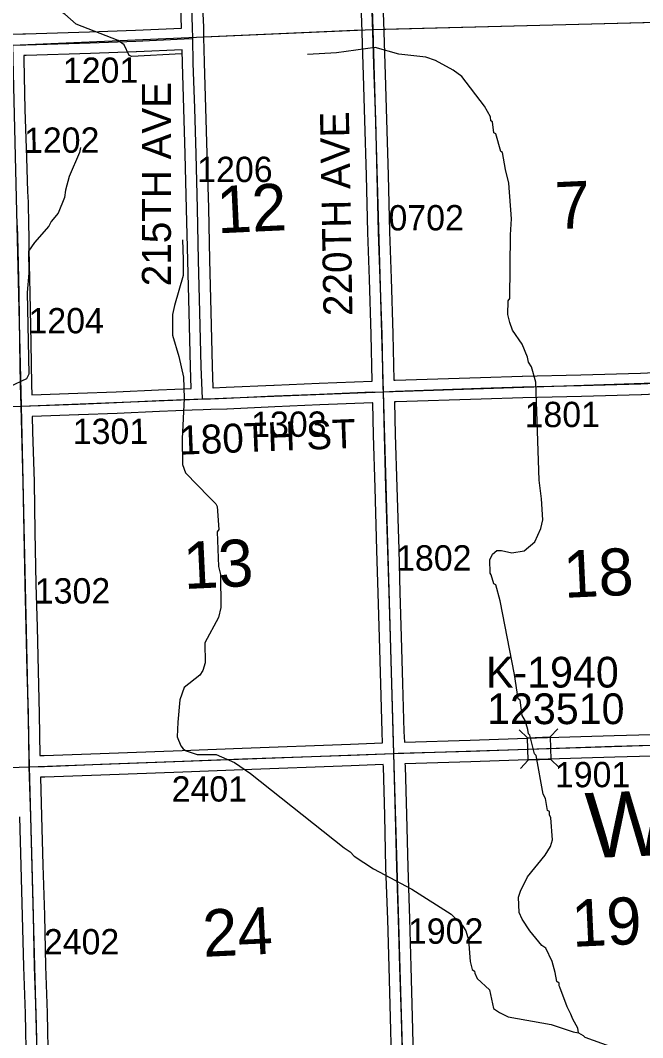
# Model space of a CAD drawing. Extents: x 128.7 to 185.5, y -21.4 to 12.6.
# Drawn here: x 145.06 to 146.778, y -5.142 to -2.33 of the extents above; entities that cross this region are included whole.
import ezdxf

# ---------------------------------------------------------------- set-up
doc = ezdxf.new("R2010")
doc.units = 0
for name, color, linetype in [('tdCoHydroRiver', 7, 'Continuous'), ('tdCoSecRdNmbr', 7, 'Continuous'), ('tdCoSecRdTxt', 7, 'Continuous'), ('tdCoSecRteBand', 7, 'Continuous'), ('tdCoSecRteCL', 7, 'Continuous'), ('tdCoSectLine', 7, 'Continuous'), ('tdCoSectLinePart', 7, 'Continuous'), ('tdCoSectNmbr', 7, 'Continuous'), ('tdCoStrucSec', 7, 'Continuous'), ('tdCoStrucSecCoName', 7, 'Continuous'), ('tdCoStrucSecFHWANum', 7, 'Continuous'), ('tdCoSurfAsphalt', 7, 'Continuous'), ('tdCoSurfGravel', 7, 'Continuous'), ('tdCoTwpBndryShd', 7, 'Continuous'), ('tdCoTwpNameTxt', 7, 'Continuous')]:
    doc.layers.add(name, color=color, linetype=linetype)

msp = doc.modelspace()

# ---------------------------------------------------------------- linework, layer by layer
at = {"layer": 'tdCoHydroRiver'}
for points in [[(145.5048, -2.4228), (145.3677, -2.4304), (145.3597, -2.4275), (145.3461, -2.398), (145.33, -2.3859), (145.2133, -2.3408), (145.1824, -2.3134), (145.1453, -2.2894), (145.0956, -2.2657), (144.9806, -2.2222)], [(146.6004, -5.128), (146.5984, -5.1154), (146.585, -5.0906), (146.5798, -5.0766), (146.5696, -5.0564), (146.5489, -5.0018), (146.5472, -4.9987), (146.547, -4.9909), (146.5405, -4.9863), (146.5365, -4.9612), (146.5277, -4.9315), (146.5107, -4.8942), (146.4994, -4.8867), (146.4665, -4.8467), (146.4449, -4.8143), (146.4364, -4.7956), (146.435, -4.7531), (146.4408, -4.7371), (146.46, -4.697), (146.5085, -4.637), (146.5235, -4.6129), (146.5293, -4.5953), (146.5241, -4.534), (146.5207, -4.5262), (146.5204, -4.5167), (146.5155, -4.5137), (146.5097, -4.4808), (146.503, -4.4684), (146.4837, -4.3617), (146.4788, -4.3571), (146.4661, -4.3055), (146.4628, -4.3024), (146.4608, -4.2898), (146.4537, -4.2648), (146.4454, -4.2509), (146.4392, -4.2085), (146.4344, -4.2055), (146.4243, -4.138), (146.3845, -3.9341), (146.372, -3.8903), (146.3671, -3.8873), (146.36, -3.8623), (146.3567, -3.8577), (146.3555, -3.8214), (146.3629, -3.8054), (146.3752, -3.7955), (146.3878, -3.7951), (146.4164, -3.8021), (146.4509, -3.7962), (146.4801, -3.7716), (146.4963, -3.7348), (146.5018, -3.7109), (146.4983, -3.6526), (146.4919, -3.6008), (146.483, -3.3296), (146.4705, -3.2874), (146.4622, -3.2751), (146.4602, -3.2609), (146.4448, -3.2251), (146.4183, -3.1865), (146.4113, -3.1647), (146.4058, -3.1428), (146.4062, -3.1049), (146.4107, -3.0984), (146.4128, -2.9232), (146.4161, -2.8789), (146.4081, -2.7797), (146.399, -2.7422), (146.3911, -2.6951), (146.3863, -2.6921), (146.3721, -2.6436), (146.3672, -2.6406), (146.3631, -2.6108), (146.3583, -2.6078), (146.3579, -2.5967), (146.3412, -2.5673), (146.2785, -2.4857), (146.2543, -2.4676), (146.206, -2.4408), (146.1789, -2.4322), (146.1045, -2.4236), (146.0392, -2.4052), (145.9323, -2.4198), (145.852, -2.424)], [(145.226, -2.6812), (145.2233, -2.6955), (145.1939, -2.7612), (145.1841, -2.7994), (145.1817, -2.82), (145.1641, -2.8632), (145.1444, -2.8859), (145.1385, -2.8987), (145.0989, -2.9442), (145.0824, -2.9684), (145.0828, -3.0284), (145.0782, -3.0822), (145.0825, -3.3077), (145.0766, -3.3205), (145.0626, -3.3273), (145.0237, -3.346)], [(145.5074, -2.9371), (145.5092, -2.9907), (145.5091, -3.0349), (145.485, -3.1178), (145.4795, -3.1432), (145.4798, -3.2), (145.4975, -3.2594), (145.5104, -3.3158), (145.5123, -3.3741), (145.5065, -3.4863), (145.5073, -3.5573), (145.5159, -3.5807), (145.5813, -3.648), (145.5992, -3.6664), (145.6026, -3.6741), (145.6079, -3.7371), (145.6033, -3.7436), (145.6065, -3.8397), (145.612, -3.8616), (145.6134, -3.9531), (145.6064, -3.9802), (145.5692, -4.0508), (145.5695, -4.1061), (145.5638, -4.1268), (145.5548, -4.1397), (145.5117, -4.1742), (145.5002, -4.2078), (145.4943, -4.2695), (145.4925, -4.3106), (145.5028, -4.3355), (145.5094, -4.3432), (145.5175, -4.3492), (145.5478, -4.3593), (145.5999, -4.3591), (145.6511, -4.3811), (145.6947, -4.4113), (145.954, -4.6174), (145.9701, -4.6279), (145.9815, -4.6401), (146.0347, -4.6747), (146.1408, -4.7312), (146.2488, -4.8002), (146.2797, -4.8308), (146.2897, -4.8462), (146.2969, -4.8712), (146.302, -4.931), (146.3074, -4.953), (146.3139, -4.9575), (146.3141, -4.9638), (146.3209, -4.9778), (146.3551, -5.0098), (146.3662, -5.0615), (146.3824, -5.072), (146.4064, -5.0839), (146.5255, -5.1052), (146.5861, -5.1253), (146.6004, -5.128), (146.6133, -5.1355), (146.6182, -5.14), (146.7459, -5.1863)]]:
    msp.add_lwpolyline(points, dxfattribs=at)
at = {"layer": 'tdCoSecRteBand'}
for points in [[(145.5915, -3.3455), (145.6278, -3.3443), (145.7598, -3.3381), (145.7599, -3.3381), (145.76, -3.3381), (145.8843, -3.3332), (146.0308, -3.3272), (146.031, -3.3272), (146.031, -3.3271), (146.0311, -3.3271), (146.0283, -3.1987), (146.0234, -3.0453), (146.0189, -2.9168), (146.0189, -2.9167), (146.0189, -2.9165), (146.015, -2.7592), (146.0108, -2.606), (146.0068, -2.4817), (146.0022, -2.3351), (145.997, -2.1964)], [(146.0569, -2.1941), (146.0621, -2.3329), (146.0621, -2.333), (146.0621, -2.3331), (146.0668, -2.4798), (146.0668, -2.4798), (146.0668, -2.4798), (146.0708, -2.6041), (146.0708, -2.6042), (146.0708, -2.6042), (146.0749, -2.7576), (146.0749, -2.7577), (146.0749, -2.7577), (146.0789, -2.9149), (146.0833, -3.0432), (146.0833, -3.0433), (146.0833, -3.0433), (146.0883, -3.1969), (146.0883, -3.1971), (146.0883, -3.1973), (146.091, -3.3247)], [(145.0367, -2.3683), (145.0664, -2.367), (145.0664, -2.3676), (145.067, -2.3676), (145.0735, -2.3674), (145.2509, -2.362), (145.3774, -2.3573), (145.5049, -2.3514), (145.5048, -2.3509), (145.5048, -2.3497), (145.5029, -2.2966)], [(145.5628, -2.2937), (145.5648, -2.3477), (145.5648, -2.348), (145.5648, -2.3483), (145.5654, -2.3795), (145.5665, -2.4092), (145.566, -2.4092), (145.5668, -2.4476), (145.5712, -2.5714), (145.5712, -2.5716), (145.5712, -2.5717), (145.5747, -2.6987), (145.5747, -2.6987), (145.5747, -2.6987), (145.5786, -2.8494), (145.5786, -2.8495), (145.5786, -2.8495), (145.5818, -2.992), (145.5855, -3.1355), (145.5855, -3.1355), (145.5855, -3.1356), (145.589, -3.2857), (145.5914, -3.3454), (145.5915, -3.3454), (145.5915, -3.3455)], [(145.091, -3.3649), (145.2183, -3.3605), (145.3242, -3.3563), (145.4413, -3.3512), (145.4413, -3.3512), (145.4414, -3.3512), (145.5315, -3.3477), (145.529, -3.2879), (145.529, -3.2876), (145.529, -3.2874), (145.5255, -3.137), (145.5218, -2.9935), (145.5218, -2.9935), (145.5218, -2.9934), (145.5186, -2.8509), (145.5147, -2.7003), (145.5112, -2.5735), (145.5068, -2.4495), (145.5068, -2.4493), (145.5068, -2.4491), (145.506, -2.4114), (145.38, -2.4173), (145.3799, -2.4173), (145.3797, -2.4173), (145.253, -2.422), (145.2529, -2.422), (145.2528, -2.422), (145.0752, -2.4274), (145.0751, -2.4274), (145.0751, -2.4274), (145.0691, -2.4276), (145.0696, -2.4381), (145.0696, -2.4385), (145.0696, -2.4389), (145.0721, -2.5763), (145.0763, -2.71), (145.0795, -2.803), (145.0807, -2.8325), (145.0807, -2.8328), (145.0807, -2.8332), (145.082, -2.8963), (145.0827, -2.9262), (145.0827, -2.9262), (145.0834, -2.9621), (145.0834, -2.9621), (145.0834, -2.9622), (145.0859, -3.0845), (145.0859, -3.0845), (145.0859, -3.0845), (145.0884, -3.2216), (145.0884, -3.2217), (145.0884, -3.2217), (145.0903, -3.3365), (145.091, -3.3649)], [(146.091, -3.3247), (146.094, -3.3245), (146.0943, -3.3245), (146.0946, -3.3245), (146.3304, -3.3169), (146.3304, -3.3169), (146.3304, -3.3169), (146.4456, -3.3132), (146.4457, -3.3132), (146.4458, -3.3132), (146.6075, -3.3095), (146.7716, -3.3048), (146.8695, -3.3001)], [(146.8722, -3.3601), (146.7742, -3.3647), (146.7739, -3.3648), (146.7736, -3.3648), (146.6091, -3.3695), (146.6091, -3.3695), (146.609, -3.3695), (146.4473, -3.3732), (146.3323, -3.3768), (146.0969, -3.3845), (146.0933, -3.3847), (146.0925, -3.3847), (146.0949, -3.4748), (146.0989, -3.6205), (146.1043, -3.7928), (146.1043, -3.7928), (146.1043, -3.7928), (146.1077, -3.9115), (146.1077, -3.9115), (146.1077, -3.9115), (146.1112, -4.0338), (146.1151, -4.1627), (146.1151, -4.1627), (146.1151, -4.1628), (146.1188, -4.2952), (146.1198, -4.325)], [(145.1137, -4.3621), (145.1251, -4.3618), (145.2797, -4.3561), (145.5063, -4.3477), (145.6717, -4.3416), (145.6718, -4.3416), (145.6718, -4.3416), (145.9709, -4.3305), (146.0596, -4.3271), (146.0596, -4.3271), (146.0598, -4.3271), (146.0589, -4.297), (146.0589, -4.2969), (146.0589, -4.2969), (146.0552, -4.1645), (146.0512, -4.0356), (146.0512, -4.0355), (146.0512, -4.0355), (146.0478, -3.9132), (146.0443, -3.7946), (146.0389, -3.6223), (146.0389, -3.6222), (146.0389, -3.6221), (146.0349, -3.4764), (146.0349, -3.4764), (146.0349, -3.4764), (146.0326, -3.3873), (146.0321, -3.3872), (145.8867, -3.3931), (145.8867, -3.3931), (145.8867, -3.3931), (145.7625, -3.398), (145.6304, -3.4042), (145.6302, -3.4042), (145.63, -3.4042), (145.5855, -3.4057), (145.5639, -3.4065), (145.5339, -3.4078), (145.5339, -3.4077), (145.5338, -3.4077), (145.4438, -3.4111), (145.3268, -3.4163), (145.3267, -3.4163), (145.3266, -3.4163), (145.2206, -3.4205), (145.2205, -3.4205), (145.2204, -3.4205), (145.0925, -3.4249), (145.0935, -3.4667), (145.0977, -3.6057), (145.0977, -3.606), (145.0977, -3.6062), (145.0997, -3.744), (145.1024, -3.8881), (145.1056, -4.0068), (145.1056, -4.0069), (145.1056, -4.0069), (145.1086, -4.1274), (145.1118, -4.2463), (145.1118, -4.2464), (145.1118, -4.2466), (145.1137, -4.3621)], [(146.1198, -4.325), (146.3012, -4.3199), (146.4846, -4.3132), (146.4847, -4.3132), (146.4848, -4.3132), (146.6995, -4.3065), (146.6996, -4.3065), (146.6996, -4.3065), (146.87, -4.3016)], [(146.8717, -4.3616), (146.7014, -4.3665), (146.4867, -4.3732), (146.3033, -4.3798), (146.3032, -4.3798), (146.3031, -4.3798), (146.1216, -4.385), (146.1216, -4.385), (146.1218, -4.3908), (146.1218, -4.3909), (146.1218, -4.3909), (146.1255, -4.5261), (146.1255, -4.5261), (146.1255, -4.5262), (146.129, -4.6705), (146.1341, -4.8131), (146.1341, -4.8132), (146.1341, -4.8133), (146.1378, -4.9455), (146.1418, -5.0843), (146.1418, -5.0844), (146.1418, -5.0844), (146.1445, -5.1934)], [(146.0845, -5.1949), (146.0818, -5.086), (146.0779, -4.9472), (146.0779, -4.9472), (146.0779, -4.9472), (146.0742, -4.8151), (146.069, -4.6725), (146.069, -4.6723), (146.069, -4.6721), (146.0655, -4.5276), (146.0618, -4.3926), (146.0617, -4.3871), (145.9731, -4.3904), (145.9731, -4.3904), (145.9731, -4.3904), (145.674, -4.4015), (145.5085, -4.4077), (145.5085, -4.4077), (145.5085, -4.4077), (145.2819, -4.4161), (145.2819, -4.4161), (145.2819, -4.4161), (145.1272, -4.4217), (145.1272, -4.4218), (145.1271, -4.4218), (145.1152, -4.4221), (145.1182, -4.5298), (145.1182, -4.5299), (145.1182, -4.5299), (145.1216, -4.6652), (145.1258, -4.8033), (145.1258, -4.8034), (145.1258, -4.8035), (145.1288, -4.9441), (145.1335, -5.0734), (145.1335, -5.0736), (145.1335, -5.0738), (145.1364, -5.2193)], [(145.0765, -5.2206), (145.0735, -5.0753), (145.0688, -4.9461), (145.0688, -4.9458), (145.0688, -4.9456), (145.0659, -4.8049), (145.0617, -4.667), (145.0617, -4.6669), (145.0617, -4.6668), (145.0582, -4.5315)]]:
    msp.add_lwpolyline(points, dxfattribs=at)
at = {"layer": 'tdCoSecRteCL'}
for points in [[(145.5354, -2.3803), (145.5348, -2.3488), (145.5328, -2.2948), (145.5304, -2.2645), (145.5286, -2.2585), (145.5265, -2.2526), (145.524, -2.2469), (145.5212, -2.2413), (145.518, -2.2359), (145.5145, -2.2307), (145.5106, -2.2258), (145.488, -2.195), (145.4554, -2.1511), (145.4448, -2.1363), (145.4415, -2.1307)], [(146.0618, -3.3563), (146.0615, -3.3461), (146.0583, -3.1979), (146.0533, -3.0443), (146.0489, -2.9158), (146.045, -2.7585), (146.0408, -2.6051), (146.0368, -2.4808), (146.0321, -2.334), (146.027, -2.1952), (146.0233, -2.1095)], [(145.0378, -2.3983), (145.0743, -2.3974), (145.2519, -2.392), (145.3786, -2.3873), (145.5118, -2.3811), (145.5354, -2.3803)], [(145.5627, -3.3765), (145.559, -3.2867), (145.5555, -3.1363), (145.5518, -2.9927), (145.5486, -2.8502), (145.5447, -2.6995), (145.5412, -2.5725), (145.5368, -2.4485), (145.5354, -2.3803)], [(145.0618, -3.396), (145.0603, -3.3371), (145.0584, -3.2222), (145.0559, -3.0851), (145.0534, -2.9628), (145.0521, -2.897)], [(146.0618, -3.3563), (146.0956, -3.3545), (146.3314, -3.3469), (146.4465, -3.3432), (146.6083, -3.3395), (146.7728, -3.3348), (146.8709, -3.3301), (147.0593, -3.3234)], [(145.5627, -3.3765), (145.5844, -3.3757), (145.629, -3.3742), (145.7612, -3.3681), (145.8855, -3.3631), (146.032, -3.3572), (146.0401, -3.3575), (146.0618, -3.3563)], [(146.0907, -4.356), (146.0889, -4.2961), (146.0852, -4.1636), (146.0812, -4.0346), (146.0778, -3.9123), (146.0743, -3.7937), (146.0689, -3.6213), (146.0649, -3.4756), (146.0618, -3.3563)], [(145.0618, -3.396), (145.2194, -3.3905), (145.3254, -3.3863), (145.4426, -3.3811), (145.5627, -3.3765)], [(145.0843, -4.3931), (145.084, -4.3812), (145.0818, -4.2471), (145.0786, -4.1282), (145.0756, -4.0076), (145.0724, -3.8888), (145.0697, -3.7445), (145.0677, -3.6066), (145.0635, -3.4676), (145.0618, -3.396)], [(146.0907, -4.356), (146.1032, -4.3555), (146.3022, -4.3498), (146.4857, -4.3432), (146.7005, -4.3365), (146.8709, -4.3316), (147.078, -4.3249), (147.0934, -4.3244)], [(145.0843, -4.3931), (145.1261, -4.3918), (145.2808, -4.3861), (145.5074, -4.3777), (145.6729, -4.3715), (145.972, -4.3605), (146.0907, -4.356)], [(146.1502, -6.358), (146.1488, -6.3081), (146.1456, -6.2164), (146.1419, -6.0805), (146.1374, -5.9335), (146.133, -5.8008), (146.1283, -5.647), (146.1239, -5.4968), (146.1187, -5.3412), (146.1145, -5.1942), (146.1118, -5.0852), (146.1078, -4.9464), (146.1041, -4.8142), (146.099, -4.6714), (146.0955, -4.5269), (146.0918, -4.3917), (146.0907, -4.356)], [(144.0777, -4.4259), (144.1257, -4.4246), (144.2342, -4.4219), (144.4894, -4.414), (144.6566, -4.4083), (144.7922, -4.4034), (144.8867, -4.3992), (145.0843, -4.3931)], [(145.1408, -6.3946), (145.1385, -6.3085), (145.1353, -6.1832), (145.1314, -6.0436), (145.1274, -5.9114), (145.1235, -5.795), (145.1185, -5.6407), (145.1141, -5.4989), (145.1102, -5.3635), (145.1065, -5.2199), (145.1035, -5.0745), (145.0988, -4.945), (145.0959, -4.8042), (145.0917, -4.6661), (145.0882, -4.5307), (145.0843, -4.3931)]]:
    msp.add_lwpolyline(points, dxfattribs=at)
at = {"layer": 'tdCoSectLine'}
for points in [[(146.001, -1.3445), (146.0324, -2.3549)], [(146.0324, -2.3549), (147.0272, -2.3297)], [(145.0374, -2.3983), (146.0324, -2.3549)], [(146.0324, -2.3549), (146.0614, -3.3563)], [(145.0374, -2.3983), (145.0614, -3.396)], [(146.0614, -3.3563), (147.0589, -3.3234)], [(145.0614, -3.396), (146.0614, -3.3563)], [(146.0614, -3.3563), (146.0903, -4.356)], [(144.0615, -3.4275), (145.0614, -3.396)], [(145.0614, -3.396), (145.084, -4.3931)], [(146.0903, -4.356), (147.093, -4.3244)], [(145.084, -4.3931), (146.0903, -4.356)], [(146.0903, -4.356), (146.1189, -5.3582)], [(144.0773, -4.4259), (145.084, -4.3931)], [(145.084, -4.3931), (145.1107, -5.3945)]]:
    msp.add_lwpolyline(points, dxfattribs=at)
at = {"layer": 'tdCoSectLinePart'}
for points in [[(146.0624, -2.3542), (146.9971, -2.3304)], [(145.5649, -2.3753), (146.002, -2.3562)]]:
    msp.add_lwpolyline(points, dxfattribs=at)
at = {"layer": 'tdCoStrucSec'}
for p, q in [((146.46, -4.3127), (146.4372, -4.2912)), ((146.5225, -4.3107), (146.544, -4.2879)), ((146.4619, -4.3752), (146.4405, -4.398)), ((146.5245, -4.3733), (146.5473, -4.3947))]:
    msp.add_line(p, q, dxfattribs=at)
msp.add_lwpolyline([(146.46, -4.3127), (146.5225, -4.3107), (146.5245, -4.3733), (146.4619, -4.3752)], close=True, dxfattribs=at)
at = {"layer": 'tdCoSurfAsphalt'}
msp.add_lwpolyline([(144.8867, -4.3992), (145.0843, -4.3931), (145.1261, -4.3918), (145.2808, -4.3861), (145.5074, -4.3777), (145.6729, -4.3715), (145.972, -4.3605), (146.0907, -4.356), (146.1032, -4.3555), (146.3022, -4.3498), (146.4857, -4.3432), (146.7005, -4.3365), (146.8709, -4.3316), (147.078, -4.3249), (147.0934, -4.3244)], dxfattribs=at)
at = {"layer": 'tdCoSurfGravel'}
for points in [[(146.0907, -4.356), (146.0889, -4.2961), (146.0852, -4.1636), (146.0812, -4.0346), (146.0778, -3.9123), (146.0743, -3.7937), (146.0689, -3.6213), (146.0649, -3.4756), (146.0618, -3.3563), (146.0615, -3.3461), (146.0583, -3.1979), (146.0533, -3.0443), (146.0489, -2.9158), (146.045, -2.7585), (146.0408, -2.6051), (146.0368, -2.4808), (146.0321, -2.334), (146.027, -2.1952), (146.0233, -2.1095)], [(145.5627, -3.3765), (145.559, -3.2867), (145.5555, -3.1363), (145.5518, -2.9927), (145.5486, -2.8502), (145.5447, -2.6995), (145.5412, -2.5725), (145.5368, -2.4485), (145.5354, -2.3803), (145.5348, -2.3488), (145.5328, -2.2948)], [(145.0378, -2.3983), (145.0743, -2.3974), (145.2519, -2.392), (145.3786, -2.3873), (145.5118, -2.3811), (145.5354, -2.3803)], [(145.1102, -5.3635), (145.1065, -5.2199), (145.1035, -5.0745), (145.0988, -4.945), (145.0959, -4.8042), (145.0917, -4.6661), (145.0882, -4.5307), (145.0843, -4.3931), (145.084, -4.3812), (145.0818, -4.2471), (145.0786, -4.1282), (145.0756, -4.0076), (145.0724, -3.8888), (145.0697, -3.7445), (145.0677, -3.6066), (145.0635, -3.4676), (145.0618, -3.396), (145.0603, -3.3371), (145.0584, -3.2222)], [(146.0618, -3.3563), (146.0956, -3.3545), (146.3314, -3.3469), (146.4465, -3.3432), (146.6083, -3.3395), (146.7728, -3.3348), (146.8709, -3.3301)], [(145.5627, -3.3765), (145.5844, -3.3757), (145.629, -3.3742), (145.7612, -3.3681), (145.8855, -3.3631), (146.032, -3.3572), (146.0401, -3.3575), (146.0618, -3.3563)], [(145.0618, -3.396), (145.2194, -3.3905), (145.3254, -3.3863), (145.4426, -3.3811), (145.5627, -3.3765)], [(146.1657, -6.8574), (146.1641, -6.8048), (146.1616, -6.7155), (146.1569, -6.57), (146.1525, -6.4383), (146.1502, -6.358), (146.1488, -6.3081), (146.1456, -6.2164), (146.1419, -6.0805), (146.1374, -5.9335), (146.133, -5.8008), (146.1283, -5.647), (146.1239, -5.4968), (146.1187, -5.3412), (146.1145, -5.1942), (146.1118, -5.0852), (146.1078, -4.9464), (146.1041, -4.8142), (146.099, -4.6714), (146.0955, -4.5269), (146.0918, -4.3917), (146.0907, -4.356), (146.0907, -4.356)]]:
    msp.add_lwpolyline(points, dxfattribs=at)
at = {"layer": 'tdCoTwpBndryShd'}
msp.add_lwpolyline([(145.7753, 4.6779), (145.8126, 3.6695), (145.8481, 2.667), (145.8861, 1.6603), (145.9237, 0.6571), (145.9624, -0.3451), (146.001, -1.3445), (146.0324, -2.3549), (146.0614, -3.3563), (146.0903, -4.356), (146.1189, -5.3582), (146.1498, -6.358), (146.1796, -7.3579)], dxfattribs=at)

# ---------------------------------------------------------------- texts
at = {"layer": 'tdCoSecRdNmbr'}
for s, rotation, p in [('1201', 0.1103, (145.1771, -2.503)), ('1202', 0.1102, (145.0696, -2.6963)), ('1206', 0.1106, (145.5479, -2.7772)), ('0702', 0.111, (146.076, -2.9108)), ('1204', 0.1102, (145.082, -3.1953)), ('1801', 0.1112, (146.4519, -3.4545)), ('1301', 0.1103, (145.2043, -3.501)), ('1303', 0.1107, (145.6967, -3.4814)), ('1802', 0.1109, (146.097, -3.851)), ('1302', 0.1102, (145.0994, -3.942)), ('1901', 0.1113, (146.5356, -4.4498)), ('2401', 0.1105, (145.4774, -4.4894)), ('1902', 0.1109, (146.1298, -4.8823)), ('2402', 0.1102, (145.1245, -4.9117))]:
    msp.add_text(s, height=0.07, rotation=rotation, dxfattribs=at).set_placement(p)
at = {"layer": 'tdCoSecRdTxt'}
for s, rotation, p in [('215TH AVE', 90, (145.4752, -3.0651)), ('220TH AVE', 91, (145.9766, -3.1466)), ('180TH ST', 2.2387, (145.4997, -3.5306))]:
    msp.add_text(s, height=0.08, rotation=rotation, dxfattribs=at).set_placement(p)
at = {"layer": 'tdCoSectNmbr'}
for s, rotation, p in [('12', 2.663, (145.6045, -2.9188)), ('7', 2.6636, (146.5391, -2.9074)), ('13', 2.6629, (145.512, -3.9019)), ('18', 2.6636, (146.5618, -3.9263)), ('19', 2.6636, (146.5842, -4.8909)), ('24', 2.6629, (145.5655, -4.9185))]:
    msp.add_text(s, height=0.13, rotation=rotation, dxfattribs=at).set_placement(p)
at = {"layer": 'tdCoStrucSecCoName'}
msp.add_text('K-1940', height=0.085, dxfattribs=at).set_placement((146.3453, -4.1741))
at = {"layer": 'tdCoStrucSecFHWANum'}
msp.add_text('123510', height=0.085, dxfattribs=at).set_placement((146.3484, -4.2752))
at = {"layer": 'tdCoTwpNameTxt'}
msp.add_text('WELTON', height=0.18, rotation=2.3163, dxfattribs=at).set_placement((146.6238, -4.6457))

doc.saveas('drawing.dxf')
